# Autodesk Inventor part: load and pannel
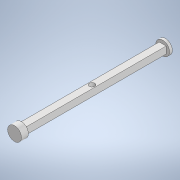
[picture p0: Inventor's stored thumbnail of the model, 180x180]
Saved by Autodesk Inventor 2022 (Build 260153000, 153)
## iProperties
Created: 2021-07
Part Number: load and pannel
Material: Generic
Document SubType Name: Modeling
Designer: 91876
Density: 1 g/cm^3
Appearance: Default
Author: 91876
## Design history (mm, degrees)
sketch "Sketch1"
  geometry: C1 r 25 at (0, 0); 1 further point
  constraints: 1 centre point, 1 coincident
  dimensions: "d0" = 50 diameter of C1
extrude "Extrusion1" new body sketch "Sketch1" distance "d1" = 10; taper "d2" = 0 deg
sketch "Sketch2"
  geometry: L1 (12.5, 12.5)-(-12.5, 12.5); L2 (-12.5, 12.5)-(-12.5, -12.5); L3 (-12.5, -12.5)-(12.5, -12.5); L4 (12.5, -12.5)-(12.5, 12.5); L5 (12.5, 12.5)-(-12.5, -12.5); L6 (-12.5, 12.5)-(12.5, -12.5); 1 further point
  constraints: 12 end point, 2 midpoint, 2 parallel, 1 horizontal, 1 perpendicular
  dimensions: "d3" = 25 distance of L3.end L2.end; "d4" = 25 distance of L2.end L1.end
extrude "Extrusion2" join sketch "Sketch2" distance "d5" = 510; taper "d6" = 0 deg
sketch "Sketch4"
  geometry: C1 r 25 at (0, 0); 1 further point
  constraints: 1 centre point, 1 coincident
  dimensions: "d11" = 50 diameter of C1
extrude "Extrusion4" join sketch "Sketch4" distance "d12" = 25; taper "d13" = 0 deg
sketch "Sketch5"
  geometry: L1 (-12.5, 0)-(37.5, 0) reference; C1 r 10 at (12.5, -255); 1 further point
  constraints: 1 centre point
  dimensions: "d14" = 20 diameter of C1; "d15" = 255 distance from line of L1 C1.centre
extrude "Extrusion5" cut sketch "Sketch5" extent not by distance; stored distance "d16" = 0; taper "d17" = 0 deg
body "Solid1"
